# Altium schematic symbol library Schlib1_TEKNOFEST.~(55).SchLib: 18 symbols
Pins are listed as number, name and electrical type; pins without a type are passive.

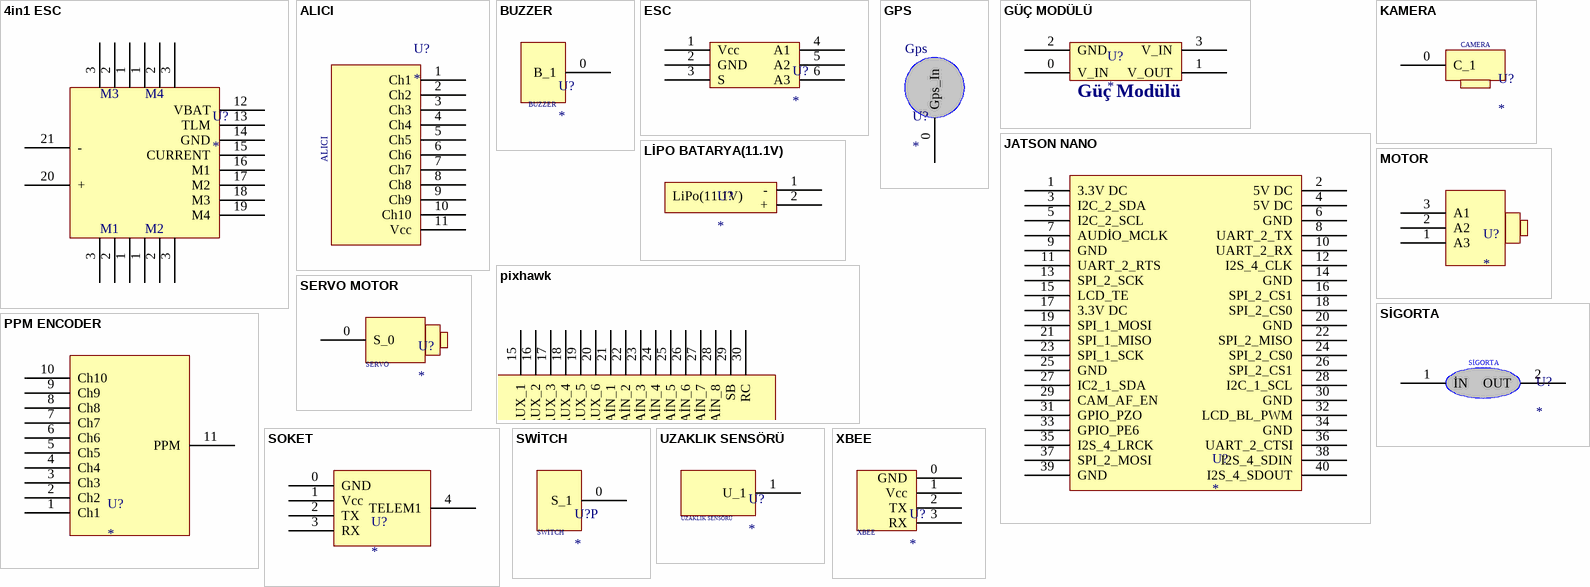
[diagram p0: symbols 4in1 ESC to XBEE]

## 4in1 ESC
designator U?
pins: 1, 1, 1, 1, 2, 2, 2, 2, 3, 3, 3, 3, 12 VBAT, 13 TLM, 14 GND, 15 CURRENT, 16 M1, 17 M2, 18 M3, 19 M4, 20 +, 21 -

## ALICI
designator U?
pins: 1 Ch1, 2 Ch2, 3 Ch3, 4 Ch4, 5 Ch5, 6 Ch6, 7 Ch7, 8 Ch8, 9 Ch9, 10 Ch10, 11 Vcc

## BUZZER
designator U?
pins: 0 B_1

## ESC
designator U?
pins: 1 Vcc, 2 GND, 3 S, 4 A1, 5 A2, 6 A3

## GPS
designator U?
pins: 0 Gps_In

## GÜÇ MODÜLÜ
designator U?
pins: 0 V_IN, 1 V_OUT, 2 GND, 3 V_IN

## JATSON NANO
designator U?
pins: 1 3.3V DC, 2 5V DC, 3 I2C_2_SDA, 4 5V DC, 5 I2C_2_SCL, 6 GND, 7 AUDİO_MCLK, 8 UART_2_TX, 9 GND, 10 UART_2_RX, 11 UART_2_RTS, 12 I2S_4_CLK, 13 SPI_2_SCK, 14 GND, 15 LCD_TE, 16 SPI_2_CS1, 17 3.3V DC, 18 SPI_2_CS0, 19 SPI_1_MOSI, 20 GND, 21 SPI_1_MISO, 22 SPI_2_MISO, 23 SPI_1_SCK, 24 SPI_2_CS0, 25 GND, 26 SPI_2_CS1, 27 IC2_1_SDA, 28 I2C_1_SCL, 29 CAM_AF_EN, 30 GND, 31 GPIO_PZO, 32 LCD_BL_PWM, 33 GPIO_PE6, 34 GND, 35 I2S_4_LRCK, 36 UART_2_CTSI, 37 SPI_2_MOSI, 38 I2S_4_SDIN, 39 GND, 40 I2S_4_SDOUT

## KAMERA
designator U?
pins: 0 C_1

## LİPO BATARYA(11.1V)
designator U?
pins: 1 -, 2 +

## MOTOR
designator U?
pins: 1 A3, 2 A2, 3 A1

## pixhawk
designator U?
pins: 1 SSR, 2 SWİTCH, 3 TELEM1, 4 TELEM2, 5 USB, 6 SPI, 7 POWER, 8 BUZZER, 9 SEİAL 4/5, 10 GPS, 11 CAN, 12 I2C, 13 ADC3.3V, 14 ADC6.6V, 15 PWM AUX_1, 16 PWM AUX_2, 17 PWM AUX_3, 18 PWM AUX_4, 19 PWM AUX_5, 20 PWM AUX_6, 21 PWM MAİN_1, 22 PWM MAİN_2, 23 PWM MAİN_3, 24 PWM MAİN_4, 25 PWM MAİN_5, 26 PWM MAİN_6, 27 PWM MAİN_7, 28 PWM MAİN_8, 29 SB, 30 RC

## PPM ENCODER
designator U?
pins: 1 Ch1, 2 Ch2, 3 Ch3, 4 Ch4, 5 Ch5, 6 Ch6, 7 Ch7, 8 Ch8, 9 Ch9, 10 Ch10, 11 PPM

## SERVO MOTOR
designator U?
pins: 0 S_0

## SİGORTA
designator U?
pins: 1 İN, 2 OUT

## SOKET
designator U?
pins: 0 GND, 1 Vcc, 2 TX, 3 RX, 4 TELEM1

## SWİTCH
designator U?P
pins: 0 S_1

## UZAKLIK SENSÖRÜ
designator U?
pins: 1 U_1

## XBEE
designator U?
pins: 0 GND, 1 Vcc, 2 TX, 3 RX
